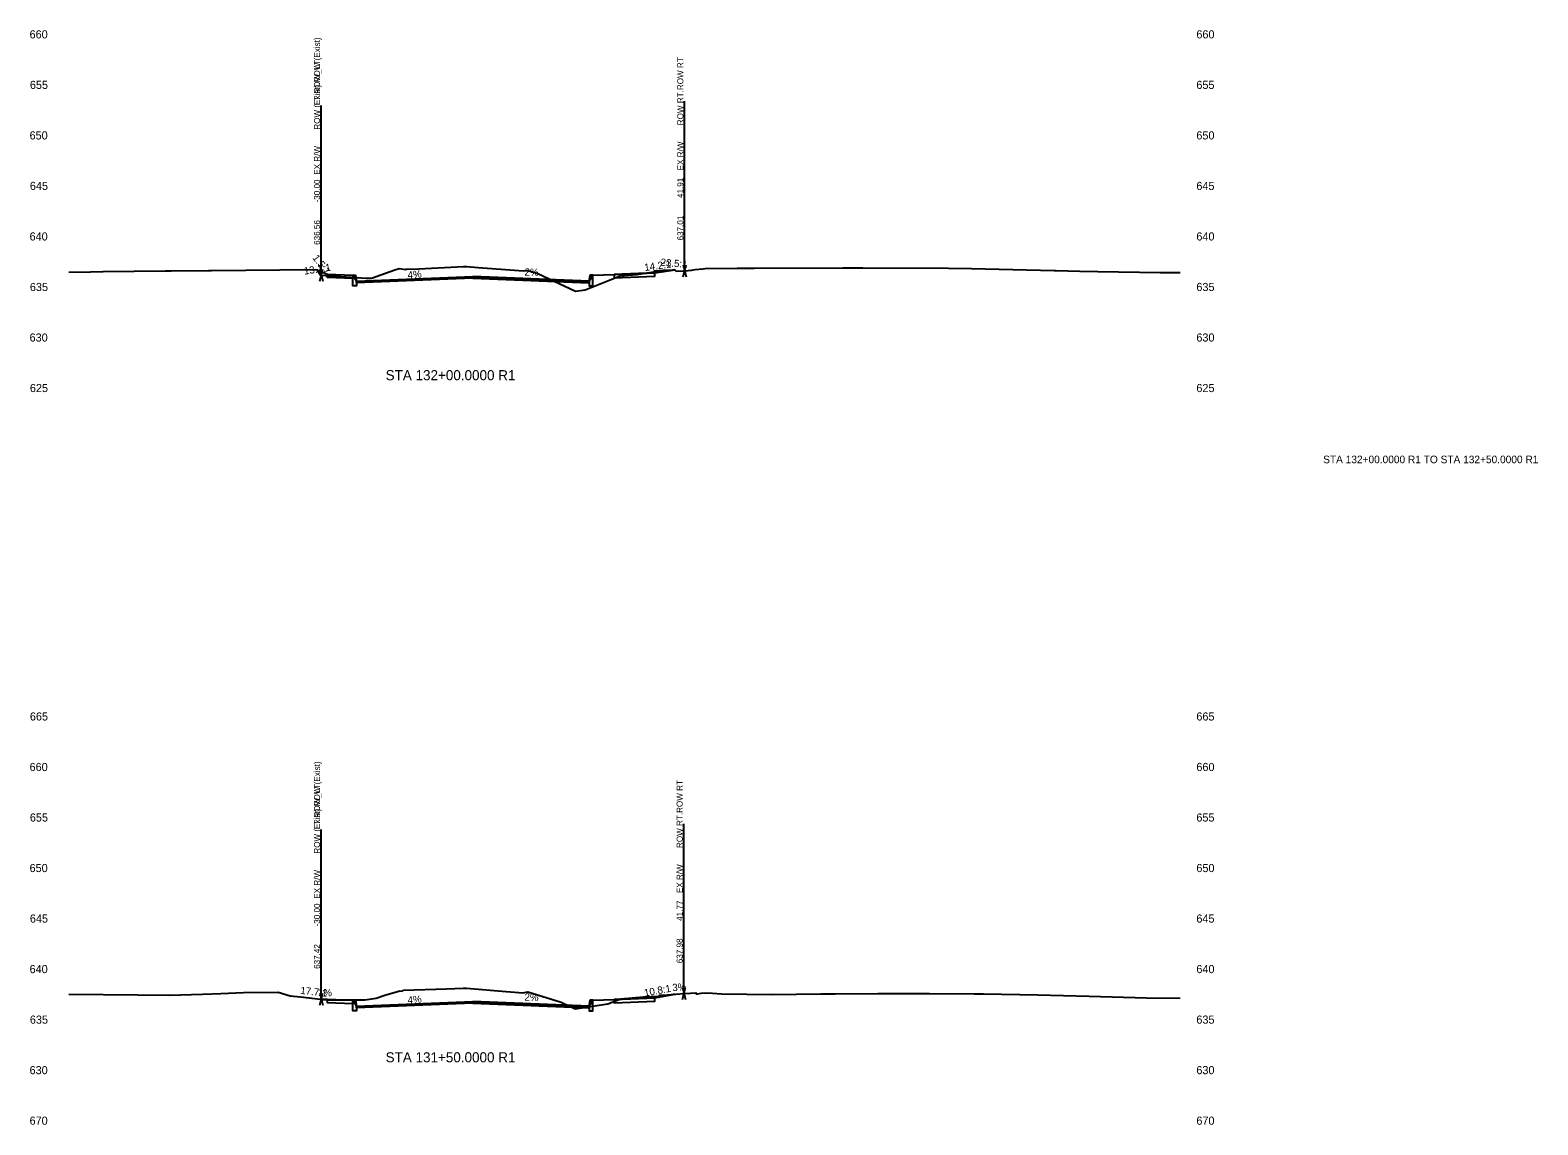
# Model space of a CAD drawing. Extents: x 2 to 741, y 16 to 2207.
# Drawn here: x 442.4 to 740.8, y 560 to 776.6 of the extents above; entities that cross this region are included whole.
import ezdxf

# ---------------------------------------------------------------- set-up
doc = ezdxf.new("R2010")
doc.units = 0
for name, color, linetype in [('BORD_text_large_2', 7, 'Continuous'), ('Draft_XS_Feature_Name', 7, 'Continuous'), ('Draft_XS_Label', 7, 'Continuous'), ('Draft_XS_Point_Label_Indicator', 7, 'Continuous'), ('Draft_XS_Terminator', 7, 'Continuous'), ('Draft_XS_Text', 7, 'Continuous'), ('E_ROW', 7, 'Continuous'), ('E_Terrain_Exterior', 7, 'Continuous'), ('E_Terrain_Points_Low', 7, 'Continuous'), ('Grade_Veg_Grass', 7, 'Continuous'), ('P_XS_Sections', 7, 'Continuous'), ('Road_Curb', 7, 'Continuous'), ('Road_Pave_Asphalt', 7, 'Continuous'), ('Road_Sidewalk', 7, 'Continuous'), ('Terrain_Design', 7, 'Continuous')]:
    doc.layers.add(name, color=color, linetype=linetype)

msp = doc.modelspace()

# ---------------------------------------------------------------- linework, layer by layer
at = {"layer": 'Draft_XS_Terminator'}
for p, q in [((500, 728.13), (500, 750.13)), ((500, 728.13), (500, 750.13)), ((571.91, 729.01), (571.91, 751.01)), ((500, 584.84), (500, 606.84)), ((500, 584.84), (500, 606.84)), ((571.77, 585.96), (571.77, 607.96))]:
    msp.add_line(p, q, dxfattribs=at)
at = {"layer": 'E_ROW'}
for p, q in [((500, 728.13), (500, 761.73)), ((500, 728.13), (500, 761.73)), ((571.91, 729.01), (571.91, 762.61)), ((499.7, 726.93), (500.3, 729.33)), ((499.7, 729.33), (500.3, 726.93)), ((499.7, 726.93), (500.3, 729.33)), ((499.7, 729.33), (500.3, 726.93)), ((571.61, 727.81), (572.21, 730.21)), ((571.61, 730.21), (572.21, 727.81)), ((500, 584.84), (500, 618.44)), ((500, 584.84), (500, 618.44)), ((571.77, 585.96), (571.77, 619.56)), ((499.7, 583.64), (500.3, 586.04)), ((499.7, 586.04), (500.3, 583.64)), ((499.7, 583.64), (500.3, 586.04)), ((499.7, 586.04), (500.3, 583.64)), ((571.47, 584.76), (572.07, 587.16)), ((571.47, 587.16), (572.07, 584.76))]:
    msp.add_line(p, q, dxfattribs=at)
at = {"layer": 'E_Terrain_Exterior'}
for points in [[(450, 728.72), (454.29, 728.82), (456.75, 728.88), (456.82, 728.88), (469.12, 728.99), (470.31, 729), (477.68, 729.06), (478.16, 729.08), (478.3, 729.08), (498.61, 729.25), (499.22, 729.18), (499.27, 729.09), (499.78, 728.22), (499.83, 728.15), (499.83, 728.15), (499.83, 728.14), (499.83, 728.14), (499.83, 728.14), (499.83, 728.14), (508.88, 727.54), (509.74, 727.54), (509.93, 727.57), (514.58, 729.2), (515.39, 729.44), (516.72, 729.26), (516.77, 729.31), (516.93, 729.33), (519.28, 729.41), (528.15, 729.85), (528.28, 729.85), (528.82, 729.85), (531.08, 729.65), (540.03, 728.97), (540.73, 729.05), (540.91, 729.09), (542.85, 728.49), (550.31, 724.97), (552.24, 725.26), (559.14, 727.98), (562.48, 728.27), (565.78, 728.77), (565.87, 728.91), (565.96, 729.02), (567.65, 729.14), (569.96, 729.22), (570.08, 729.08), (570.22, 728.91), (572.19, 729.03), (572.63, 729.08), (573.33, 729.15), (573.64, 729.19), (573.99, 729.23), (575.53, 729.39), (575.97, 729.44), (582.32, 729.51), (585.71, 729.54), (603.25, 729.61), (607.2, 729.62), (624.18, 729.54), (628.68, 729.47), (645.1, 729.06), (645.44, 729.05), (647.78, 729), (650.16, 728.95), (653.71, 728.89), (666.03, 728.7), (670, 728.67)], [(450, 585.85), (463.66, 585.69), (470, 585.64), (476.48, 585.87), (480.12, 586), (484.59, 586.16), (491.48, 586.24), (493.86, 585.53), (495.87, 585.3), (499.86, 584.85), (500.31, 584.8), (500.71, 584.76), (501.18, 584.7), (501.24, 584.69), (508.64, 584.73), (510.86, 585.02), (512.6, 585.63), (515.54, 586.49), (516.04, 586.42), (516.23, 586.59), (516.29, 586.6), (524.76, 586.88), (528.08, 587.04), (528.56, 587.04), (528.76, 587.05), (536.62, 586.37), (539.98, 586.11), (540.24, 586.14), (540.86, 586.27), (547.49, 584.25), (550.26, 582.95), (556.74, 583.92), (559.29, 584.92), (563.79, 585.32), (566.83, 585.47), (566.97, 585.64), (568.56, 585.74), (570.96, 585.92), (574.13, 586.1), (574.19, 585.9), (574.27, 585.91), (574.49, 585.93), (575.17, 586.01), (575.97, 586.1), (577.41, 586.03), (579.24, 585.93), (589.23, 585.8), (598.89, 585.88), (601.72, 585.9), (610.16, 585.94), (614.85, 585.94), (620.37, 585.95), (629.23, 585.9), (631.08, 585.89), (641.86, 585.74), (652.01, 585.43), (663.34, 585.09), (670, 585.02)]]:
    msp.add_lwpolyline(points, dxfattribs=at)
at = {"layer": 'Grade_Veg_Grass'}
for points in [[(499.25, 729.12), (501.25, 728.32), (501.25, 728.32)], [(553.75, 728.12), (558, 728.29)], [(570, 729.17), (566, 728.61), (566, 728.61)], [(570, 585.85), (566, 585.11), (566, 585.11)], [(499.25, 584.92), (499.25, 584.92), (501.25, 584.82)], [(553.75, 584.62), (558, 584.79)]]:
    msp.add_lwpolyline(points, dxfattribs=at)
at = {"layer": 'Road_Curb'}
for points in [[(507, 726.95), (507, 726.04), (506.25, 726.04), (506.25, 728.12), (506.77, 728.12), (507, 726.95)], [(553, 726.95), (553, 726.04), (553.75, 726.04), (553.75, 728.12), (553.23, 728.12), (553, 726.95)], [(507, 583.45), (507, 582.54), (506.25, 582.54), (506.25, 584.62), (506.77, 584.62), (507, 583.45)], [(553, 583.45), (553, 582.54), (553.75, 582.54), (553.75, 584.62), (553.23, 584.62), (553, 583.45)]]:
    msp.add_lwpolyline(points, dxfattribs=at)
at = {"layer": 'Road_Pave_Asphalt'}
for points in [[(530, 727.87), (530, 727.54), (507, 726.62), (507, 726.95), (530, 727.87)], [(530, 727.87), (530, 727.54), (553, 726.62), (553, 726.95), (530, 727.87)], [(530, 584.37), (530, 584.04), (507, 583.12), (507, 583.45), (530, 584.37)], [(530, 584.37), (530, 584.04), (553, 583.12), (553, 583.45), (530, 584.37)]]:
    msp.add_lwpolyline(points, dxfattribs=at)
at = {"layer": 'Road_Sidewalk'}
for points in [[(506.25, 728.12), (506.25, 727.45), (501.25, 727.65), (501.25, 728.32), (506.25, 728.12)], [(558, 728.29), (558, 727.62), (566, 727.94), (566, 728.61), (558, 728.29)], [(558, 584.79), (558, 584.12), (566, 584.44), (566, 585.11), (558, 584.79)], [(506.25, 584.62), (506.25, 583.95), (501.25, 584.15), (501.25, 584.82), (506.25, 584.62)]]:
    msp.add_lwpolyline(points, dxfattribs=at)
at = {"layer": 'Terrain_Design'}
for points in [[(499.25, 729.12), (499.25, 729.12), (501.25, 728.32), (506.25, 728.12), (506.77, 728.12), (507, 726.95), (530, 727.87), (553, 726.95), (553.23, 728.12), (553.75, 728.12), (558, 728.29), (566, 728.61), (570, 729.17)], [(499.25, 729.12), (499.25, 729.12), (501.25, 728.32), (506.25, 728.12), (506.77, 727.31), (507, 726.95), (530, 727.87), (553, 726.95), (553.23, 727.31), (553.75, 728.12), (558, 728.29), (566, 728.61), (570, 729.17)], [(499.25, 584.92), (501.25, 584.82), (506.25, 584.62), (506.77, 584.62), (507, 583.45), (530, 584.37), (553, 583.45), (553.23, 584.62), (553.75, 584.62), (558, 584.79), (566, 585.11), (570, 585.85)], [(499.25, 584.92), (501.25, 584.82), (506.25, 584.62), (506.77, 583.81), (507, 583.45), (530, 584.37), (553, 583.45), (553.23, 583.81), (553.75, 584.62), (558, 584.79), (566, 585.11), (570, 585.85)]]:
    msp.add_lwpolyline(points, dxfattribs=at)

# ---------------------------------------------------------------- texts
at = {"layer": 'BORD_text_large_2'}
msp.add_text('STA 132+00.0000 R1 TO STA 132+50.0000 R1', height=1.5, dxfattribs=at).set_placement((698.32, 690.92))
at = {"layer": 'Draft_XS_Feature_Name'}
for s, p in [('ROW (Exist).ROW (Exist)', (499.76, 756.93)), ('ROW_LT.ROW_LT', (499.76, 756.93)), ('ROW RT.ROW RT', (571.67, 757.81)), ('ROW (Exist).ROW (Exist)', (499.76, 613.64)), ('ROW_LT.ROW_LT', (499.76, 613.64)), ('ROW RT.ROW RT', (571.53, 614.76))]:
    msp.add_text(s, height=1.2, rotation=90, dxfattribs=at).set_placement(p)
at = {"layer": 'Draft_XS_Label'}
for s, p in [('-30.00', (499.76, 742.53)), ('-30.00', (499.76, 742.53)), ('41.91', (571.67, 743.41)), ('636.56', (499.76, 734.13)), ('636.56', (499.76, 734.13)), ('637.01', (571.67, 735.01)), ('-30.00', (499.76, 599.24)), ('-30.00', (499.76, 599.24)), ('41.77', (571.53, 600.36)), ('637.42', (499.76, 590.84)), ('637.42', (499.76, 590.84)), ('637.98', (571.53, 591.96))]:
    msp.add_text(s, height=1.2, rotation=90, dxfattribs=at).set_placement(p)
at = {"layer": 'Draft_XS_Point_Label_Indicator'}
for p in [(499.24, 729.11), (501.24, 728.31), (557.99, 728.28), (565.99, 728.6), (569.99, 729.16), (506.24, 728.11), (506.76, 728.11), (506.99, 726.94), (506.99, 726.02), (552.99, 726.94), (552.99, 726.02), (553.22, 728.11), (553.74, 728.11), (565.99, 585.1), (569.99, 585.84), (499.24, 584.91), (501.24, 584.81), (506.24, 584.61), (506.76, 584.61), (506.99, 583.44), (506.99, 582.52), (552.99, 583.44), (552.99, 582.52), (553.22, 584.61), (553.74, 584.61), (557.99, 584.78)]:
    msp.add_text('X', height=0.024, dxfattribs=at).set_placement(p)
at = {"layer": 'Draft_XS_Text'}
for s, height, p in [('660', 1.608, (442.26, 775)), ('660', 1.608, (673.22, 775)), ('655', 1.608, (442.32, 765)), ('655', 1.608, (673.22, 765)), ('650', 1.608, (442.26, 755)), ('650', 1.608, (673.22, 755)), ('645', 1.608, (442.32, 745)), ('645', 1.608, (673.22, 745)), ('640', 1.608, (442.26, 735)), ('640', 1.608, (673.22, 735)), ('635', 1.608, (442.32, 725)), ('635', 1.608, (673.22, 725)), ('630', 1.608, (442.26, 715)), ('630', 1.608, (673.22, 715)), ('STA 132+00.0000 R1', 1.992, (512.74, 707.35)), ('625', 1.608, (442.32, 705)), ('625', 1.608, (673.22, 705)), ('665', 1.608, (442.32, 640)), ('665', 1.608, (673.22, 640)), ('660', 1.608, (442.26, 630)), ('660', 1.608, (673.22, 630)), ('655', 1.608, (442.32, 620)), ('655', 1.608, (673.22, 620)), ('650', 1.608, (442.26, 610)), ('650', 1.608, (673.22, 610)), ('645', 1.608, (442.32, 600)), ('645', 1.608, (673.22, 600)), ('640', 1.608, (442.26, 590)), ('640', 1.608, (673.22, 590)), ('635', 1.608, (442.32, 580)), ('635', 1.608, (673.22, 580)), ('STA 131+50.0000 R1', 1.992, (512.74, 572.35)), ('630', 1.608, (442.26, 570)), ('630', 1.608, (673.22, 570)), ('670', 1.608, (442.26, 560)), ('670', 1.608, (673.22, 560))]:
    msp.add_text(s, height=height, dxfattribs=at).set_placement(p)
for s, rotation, p in [('1.5:1', 307.0074, (498.18, 731.54)), ('23.5:1', 355.1385, (567.11, 730.02)), ('13.1:1', 8.671, (496.67, 728.23)), ('4%', 4.5657, (517.14, 727.45)), ('2%', 357.7094, (540.21, 728.07)), ('14.2:1', 8.0099, (564.04, 728.94)), ('3%', 3.7268, (569.53, 586.42)), ('17.7:1', 353.5686, (495.8, 585.91)), ('1%', 359.1749, (499.32, 585.45)), ('4%', 4.5657, (517.14, 583.95)), ('2%', 357.7094, (540.21, 584.57)), ('10.8:1', 10.4528, (564.04, 585.36))]:
    msp.add_text(s, height=1.44, rotation=rotation, dxfattribs=at).set_placement(p)
at = {"layer": 'E_ROW'}
for p in [(499.76, 748.01), (499.76, 748.01), (571.67, 748.89), (499.76, 604.72), (499.76, 604.72), (571.53, 605.84)]:
    msp.add_text('EX R/W', height=1.2, rotation=90, dxfattribs=at).set_placement(p)
at = {"layer": 'E_Terrain_Points_Low'}
for p in [(529.99, 727.86), (529.99, 584.36)]:
    msp.add_text('X', height=0.024, dxfattribs=at).set_placement(p)
at = {"layer": 'P_XS_Sections'}
for p in [(450, 705), (450, 570)]:
    msp.add_text('-', height=0.0001, dxfattribs=at).set_placement(p)

doc.saveas('drawing.dxf')
